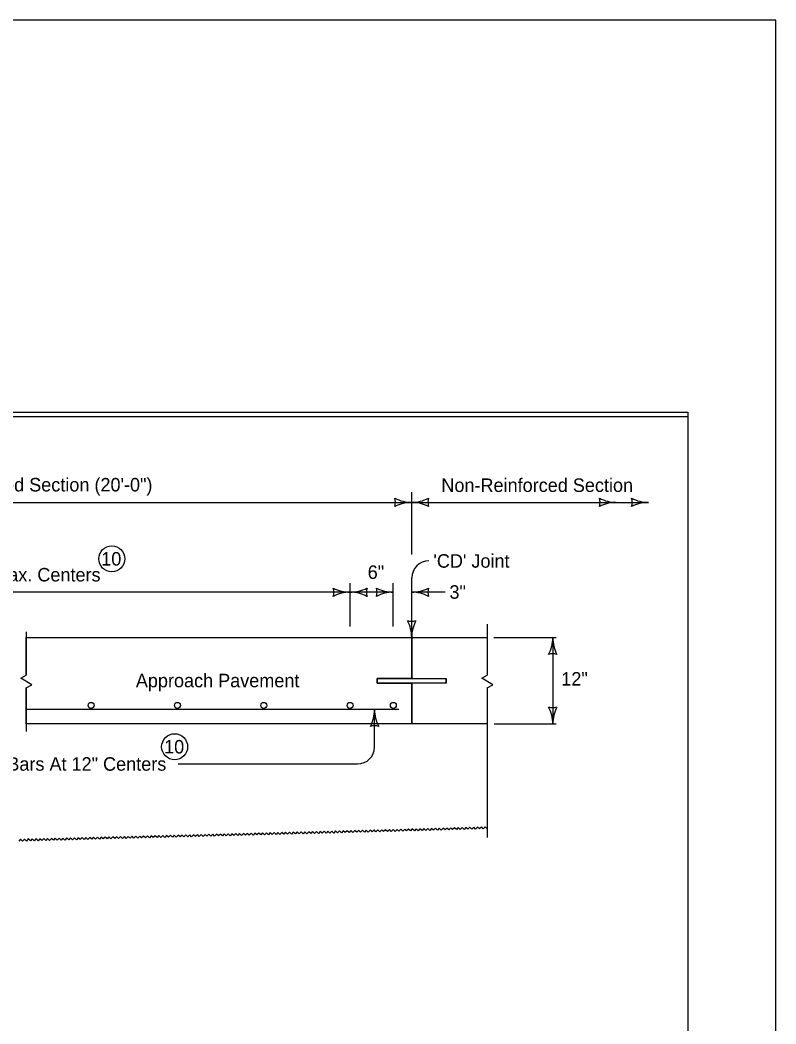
# Model space of a CAD drawing. Extents: x 10028 to 81668, y 6395 to 11634.
# Drawn here: x 19676 to 20572, y 9219 to 10409 of the extents above; entities that cross this region are included whole.
import ezdxf

# ---------------------------------------------------------------- set-up
doc = ezdxf.new("R2010")
doc.units = 0
for name, color, linetype in [('Default', 7, 'Continuous'), ('dsnCellElements', 7, 'Continuous'), ('dsnstdblockInterim', 7, 'Continuous'), ('dsnStdBlockNotModified', 7, 'Continuous'), ('dsnStdDimension', 7, 'Continuous'), ('ShtPlotIdentification', 7, 'Continuous')]:
    doc.layers.add(name, color=color, linetype=linetype)

msp = doc.modelspace()

# ---------------------------------------------------------------- linework, layer by layer
at = {"layer": 'Default'}
msp.add_lwpolyline([(17332.5, 9944), (20467.5, 9944), (20467.5, 7924), (17332.5, 7924)], close=True, dxfattribs=at)
at = {"layer": 'dsnCellElements'}
for p, q in [((20140.5, 9775.6), (20140.5, 9849.3)), ((19173.1, 9837.2), (20140.5, 9837.2)), ((20140.5, 9837.2), (20420.9, 9837.2)), ((20067.5, 9690.1), (20067.5, 9741.3)), ((20118.7, 9690.1), (20118.7, 9741.3)), ((20140.5, 9677), (20140.5, 9747.6)), ((20067.5, 9730.7), (19244.8, 9730.7)), ((20118.7, 9730.7), (20067.5, 9730.7)), ((20180.3, 9730.7), (20140.5, 9730.7)), ((19683.8, 9632.6), (19683.8, 9677)), ((19683.8, 9677), (20140.5, 9677)), ((19683.8, 9677), (20140.5, 9677)), ((20140.5, 9677), (20140.5, 9628.7)), ((20140.5, 9677), (20229.5, 9677)), ((20237.6, 9677), (20311.5, 9677)), ((20307.6, 9677), (20307.6, 9574.7)), ((19683.8, 9632.6), (19683.8, 9632.6)), ((20140.5, 9628.7), (20099.6, 9628.7)), ((20099.6, 9628.7), (20099.6, 9623)), ((20099.6, 9628.7), (20099.6, 9623)), ((20099.6, 9623), (20140.5, 9623)), ((20140.5, 9623), (20140.5, 9574.7)), ((20140.5, 9574.7), (20140.5, 9623)), ((20181.4, 9623), (20181.4, 9628.7)), ((19683.8, 9574.7), (19683.8, 9617.4)), ((20096.5, 9547.5), (20096.5, 9591.8)), ((20140.5, 9574.7), (19683.8, 9574.7)), ((20140.5, 9574.7), (19683.8, 9574.7)), ((20230, 9574.7), (20140.5, 9574.7)), ((20238.1, 9574.7), (20311.5, 9574.7)), ((19863.7, 9527.3), (20076.3, 9527.3))]:
    msp.add_line(p, q, dxfattribs=at)
for points in [[(19683.8, 9617.4), (19690.3, 9621.2), (19677.2, 9628.8), (19683.8, 9632.6)], [(19860.3, 9441.8), (19859.2, 9442.9), (19856.9, 9440.5), (19854.6, 9442.8), (19852.4, 9440.4), (19850.1, 9442.6), (19847.8, 9440.3), (19845.5, 9442.5), (19843.3, 9440.2), (19841, 9442.4), (19838.7, 9440.1), (19836.4, 9442.3), (19834.2, 9440), (19831.9, 9442.2), (19829.6, 9439.8), (19827.3, 9442), (19825.1, 9439.7), (19822.8, 9441.9), (19820.5, 9439.6), (19818.2, 9441.8), (19816, 9439.5), (19813.7, 9441.7), (19811.4, 9439.4), (19809.1, 9441.6), (19806.9, 9439.2), (19805.7, 9440.3)], [(19914.9, 9443.2), (19913.8, 9444.3), (19911.6, 9442), (19909.2, 9444.2), (19907, 9441.9), (19904.7, 9444.1), (19902.4, 9441.7), (19900.1, 9444), (19897.9, 9441.6), (19895.6, 9443.8), (19893.3, 9441.5), (19891, 9443.7), (19888.8, 9441.4), (19886.5, 9443.6), (19884.2, 9441.3), (19881.9, 9443.5), (19879.7, 9441.1), (19877.4, 9443.4), (19875.1, 9441), (19872.8, 9443.2), (19870.6, 9440.9), (19868.3, 9443.1), (19866, 9440.8), (19863.7, 9443), (19861.5, 9440.7), (19860.3, 9441.8)], [(19969.5, 9444.6), (19968.4, 9445.7), (19966.2, 9443.4), (19963.8, 9445.6), (19961.6, 9443.3), (19959.3, 9445.5), (19957.1, 9443.2), (19954.7, 9445.4), (19952.5, 9443), (19950.2, 9445.3), (19948, 9442.9), (19945.6, 9445.1), (19943.4, 9442.8), (19941.1, 9445), (19938.9, 9442.7), (19936.5, 9444.9), (19934.3, 9442.6), (19932, 9444.8), (19929.8, 9442.4), (19927.4, 9444.7), (19925.2, 9442.3), (19922.9, 9444.5), (19920.7, 9442.2), (19918.3, 9444.4), (19916.1, 9442.1), (19914.9, 9443.2)], [(20024.1, 9446.1), (20023, 9447.2), (20020.8, 9444.8), (20018.4, 9447), (20016.2, 9444.7), (20013.9, 9446.9), (20011.7, 9444.6), (20009.3, 9446.8), (20007.1, 9444.5), (20004.8, 9446.7), (20002.6, 9444.4), (20000.2, 9446.6), (19998, 9444.2), (19995.7, 9446.4), (19993.5, 9444.1), (19991.1, 9446.3), (19988.9, 9444), (19986.6, 9446.2), (19984.4, 9443.9), (19982, 9446.1), (19979.8, 9443.8), (19977.5, 9446), (19975.3, 9443.6), (19972.9, 9445.9), (19970.7, 9443.5), (19969.5, 9444.6)], [(20078.8, 9447.5), (20077.6, 9448.6), (20075.4, 9446.3), (20073, 9448.5), (20070.8, 9446.1), (20068.5, 9448.3), (20066.3, 9446), (20063.9, 9448.2), (20061.7, 9445.9), (20059.4, 9448.1), (20057.2, 9445.8), (20054.8, 9448), (20052.6, 9445.7), (20050.3, 9447.9), (20048.1, 9445.5), (20045.7, 9447.7), (20043.5, 9445.4), (20041.2, 9447.6), (20039, 9445.3), (20036.6, 9447.5), (20034.4, 9445.2), (20032.1, 9447.4), (20029.9, 9445.1), (20027.5, 9447.3), (20025.3, 9444.9), (20024.1, 9446.1)], [(20133.4, 9448.9), (20132.2, 9450), (20130, 9447.7), (20127.6, 9449.9), (20125.4, 9447.6), (20123.1, 9449.8), (20120.9, 9447.4), (20118.5, 9449.7), (20116.3, 9447.3), (20114, 9449.5), (20111.8, 9447.2), (20109.4, 9449.4), (20107.2, 9447.1), (20104.9, 9449.3), (20102.7, 9447), (20100.3, 9449.2), (20098.1, 9446.8), (20095.8, 9449.1), (20093.6, 9446.7), (20091.2, 9448.9), (20089, 9446.6), (20086.7, 9448.8), (20084.5, 9446.5), (20082.1, 9448.7), (20079.9, 9446.4), (20078.8, 9447.5)], [(20187.9, 9450.4), (20186.7, 9451.5), (20184.5, 9449.2), (20182.2, 9451.4), (20180, 9449.1), (20177.6, 9451.3), (20175.4, 9449), (20173.1, 9451.2), (20170.9, 9448.8), (20168.5, 9451.1), (20166.3, 9448.7), (20164, 9450.9), (20161.8, 9448.6), (20159.4, 9450.8), (20157.2, 9448.5), (20154.9, 9450.7), (20152.7, 9448.4), (20150.3, 9450.6), (20148.1, 9448.2), (20145.8, 9450.5), (20143.6, 9448.1), (20141.2, 9450.3), (20139, 9448), (20136.7, 9450.2), (20134.5, 9447.9), (20133.3, 9449)], [(20230, 9450.4), (20227.6, 9452.8), (20225.3, 9450.4), (20223, 9452.7), (20220.8, 9450.3), (20218.5, 9452.5), (20216.2, 9450.2), (20213.9, 9452.4), (20211.7, 9450.1), (20209.4, 9452.3), (20207.1, 9450), (20204.8, 9452.2), (20202.6, 9449.8), (20200.3, 9452.1), (20198, 9449.7), (20195.7, 9451.9), (20193.5, 9449.6), (20191.1, 9451.8), (20188.9, 9449.5), (20187.8, 9450.6)], [(19696.5, 9437.5), (19695.3, 9438.6), (19693.1, 9436.3), (19690.8, 9438.5), (19688.6, 9436.2), (19686.2, 9438.4), (19684, 9436), (19681.7, 9438.2), (19679.5, 9435.9), (19677.1, 9438.1), (19674.9, 9435.8)], [(19751.1, 9438.9), (19749.9, 9440), (19747.7, 9437.7), (19745.4, 9439.9), (19743.2, 9437.6), (19740.8, 9439.8), (19738.6, 9437.5), (19736.3, 9439.7), (19734.1, 9437.3), (19731.7, 9439.6), (19729.5, 9437.2), (19727.2, 9439.4), (19725, 9437.1), (19722.6, 9439.3), (19720.4, 9437), (19718.1, 9439.2), (19715.9, 9436.9), (19713.5, 9439.1), (19711.3, 9436.7), (19709, 9439), (19706.8, 9436.6), (19704.4, 9438.8), (19702.2, 9436.5), (19699.9, 9438.7), (19697.7, 9436.4), (19696.5, 9437.5)], [(19805.7, 9440.3), (19804.6, 9441.5), (19802.3, 9439.1), (19800, 9441.3), (19797.8, 9439), (19795.4, 9441.2), (19793.2, 9438.9), (19790.9, 9441.1), (19788.7, 9438.8), (19786.3, 9441), (19784.1, 9438.6), (19781.8, 9440.9), (19779.6, 9438.5), (19777.2, 9440.7), (19775, 9438.4), (19772.7, 9440.6), (19770.5, 9438.3), (19768.1, 9440.5), (19765.9, 9438.2), (19763.6, 9440.4), (19761.4, 9438.1), (19759, 9440.3), (19756.8, 9437.9), (19754.5, 9440.1), (19752.3, 9437.8), (19751.1, 9438.9)]]:
    msp.add_lwpolyline(points, dxfattribs=at)
for centre, start, end in [((20160.7, 9747.6), 90, 180), ((20076.3, 9547.5), 270, 0)]:
    msp.add_arc(centre, 20.2, start, end, dxfattribs=at)
at = {"layer": 'dsnstdblockInterim'}
msp.add_lwpolyline([(17332.5, 9939), (20467.5, 9939), (20467.5, 7929), (17332.5, 7929)], close=True, dxfattribs=at)
at = {"layer": 'dsnStdBlockNotModified'}
for centre, radius, start, end in [((20104.8, 9837.2), 16.4, 342.2666, 17.7333), ((20140.5, 9879.7), 42.5, 241.9275, 270), ((20140.5, 9794.7), 42.5, 90, 118.0725), ((20140.5, 9879.7), 42.5, 270, 298.0725), ((20140.5, 9794.7), 42.5, 61.9275, 90), ((20176.1, 9837.2), 16.4, 162.2666, 197.7334), ((20347.2, 9837.2), 16.4, 342.2666, 17.7333), ((20382.8, 9879.7), 42.5, 241.9275, 270), ((20382.8, 9794.7), 42.5, 90, 118.0725), ((20385.3, 9837.2), 16.4, 342.2666, 17.7333), ((20420.9, 9879.7), 42.5, 241.9275, 270), ((20420.9, 9794.7), 42.5, 90, 118.0725), ((20031.9, 9730.7), 16.4, 342.2666, 17.7333), ((20067.5, 9773.2), 42.5, 241.9275, 270), ((20067.5, 9688.2), 42.5, 90, 118.0725), ((20067.5, 9773.2), 42.5, 270, 298.0725), ((20067.5, 9688.2), 42.5, 61.9275, 90), ((20103.2, 9730.7), 16.4, 162.2666, 197.7334), ((20083.1, 9730.7), 16.4, 342.2666, 17.7333), ((20118.7, 9773.2), 42.5, 241.9275, 270), ((20118.7, 9688.2), 42.5, 90, 118.0725), ((20140.5, 9773.2), 42.5, 270, 298.0725), ((20140.5, 9688.2), 42.5, 61.9275, 90), ((20176.1, 9730.7), 16.4, 162.2666, 197.7334), ((20140.5, 9712.7), 16.4, 252.2666, 287.7333), ((20098, 9677), 42.5, 360, 28.0725), ((20183, 9677), 42.5, 151.9275, 180), ((20054, 9591.8), 42.5, 331.9275, 0), ((20139, 9591.8), 42.5, 180, 208.0725), ((20096.5, 9556.1), 16.4, 72.2666, 107.7334)]:
    msp.add_arc(centre, radius, start, end, dxfattribs=at)
at = {"layer": 'dsnStdDimension'}
msp.add_lwpolyline([(17228, 7824.5), (20572, 7824.5), (20572, 10408.5), (17228, 10408.5)], close=True, dxfattribs=at)
at = {"layer": 'ShtPlotIdentification'}
for p, q in [((20230, 9692.7), (20230, 9632.6)), ((19683.8, 9683.9), (19683.8, 9632.6)), ((20140.5, 9628.7), (20140.5, 9677)), ((20099.6, 9623), (20099.6, 9628.7)), ((20099.6, 9628.7), (20181.4, 9628.7)), ((20181.4, 9623), (20099.6, 9623)), ((20140.5, 9574.7), (20140.5, 9623)), ((20181.4, 9628.7), (20181.4, 9623)), ((19683.8, 9617.4), (19683.8, 9565.7)), ((20230, 9617.4), (20230, 9440.2)), ((20125.4, 9591.8), (19683.8, 9591.8))]:
    msp.add_line(p, q, dxfattribs=at)
for points in [[(19683.8, 9617.4), (19690.3, 9621.2), (19677.2, 9628.8), (19683.8, 9632.6)], [(20230, 9617.4), (20236.6, 9621.2), (20223.5, 9628.8), (20230, 9632.6)]]:
    msp.add_lwpolyline(points, dxfattribs=at)
for centre, radius in [((19785.1, 9770.3), 15.4), ((19760.6, 9596.7), 3.55), ((19862.9, 9596.7), 3.55), ((19965.2, 9596.7), 3.55), ((20067.5, 9596.7), 3.55), ((20118.7, 9596.7), 3.55), ((19859.6, 9547.7), 15.4)]:
    msp.add_circle(centre, radius, dxfattribs=at)
for centre, radius, start, end in [((20265.1, 9677), 42.5, 331.9275, 360), ((20350.1, 9677), 42.5, 180, 208.0725), ((20307.6, 9641.4), 16.4, 72.2666, 107.7334), ((20307.6, 9610.4), 16.4, 252.2666, 287.7333), ((20265.1, 9574.7), 42.5, 360, 28.0725), ((20350.1, 9574.7), 42.5, 151.9275, 180)]:
    msp.add_arc(centre, radius, start, end, dxfattribs=at)

# ---------------------------------------------------------------- texts
at = {"layer": 'dsnCellElements'}
for s, p in [('Single Reinforced Section (20\'-0")', (19512.4, 9850.1)), ('Non-Reinforced Section', (20175.6, 9849.5)), ('10', (19772.6, 9762.3)), ("'CD' Joint", (20166.2, 9759.8)), ('#5 Bars At 12" max. Centers', (19501.4, 9743.5)), ('6"', (20088.3, 9746.5)), ('3"', (20185.2, 9723)), ('Approach Pavement', (19813.6, 9618.1)), ('12"', (20317.7, 9620.1)), ('10', (19847.1, 9539.7)), ('#5 Bars At 12" Centers', (19631.6, 9519.3))]:
    msp.add_text(s, height=16, dxfattribs=at).set_placement(p)

doc.saveas('drawing.dxf')
